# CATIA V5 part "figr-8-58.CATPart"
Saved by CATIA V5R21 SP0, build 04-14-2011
Part number: Part1
Bounding box of the stored display mesh (mm): x -50.499 to 50.499, y -68.48 to 68.48, z -46 to 50
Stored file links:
  D:\CATIA V5R21 E-RESOURCES\CATIA-V5R21\catia-v5r21-prt\c08-catia-v5r20-prt\c08-catia-v5r21-figr-8-58.CATPart
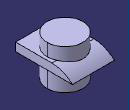
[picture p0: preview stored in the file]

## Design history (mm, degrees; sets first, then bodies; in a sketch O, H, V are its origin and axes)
Body1 (main body)
  Sketch1 on xy-plane, origin (0, 0, 0), H (1, 0, 0), V (0, 1, 0)
    line L1 (-50.499, 68.4797) -> (50.499, 68.4797)
    line L2 (50.499, 68.4797) -> (50.499, -68.4797)
    line L3 (50.499, -68.4797) -> (-50.499, -68.4797)
    line L4 (-50.499, -68.4797) -> (-50.499, 68.4797)
    axis line L5 (50.499, -68.4797) -> (-50.499, 68.4797)
    horizontal: L1 H, L3 H
    vertical: L2 V, L4 V
    midpoint: O L5
  Pad1: profile Sketch1, direction (0, 0, 1), length 20
  Fillet1: radius 71, on edge [face of Pad1 | face of Pad1]
  Body2
    Sketch2 on xy-plane, origin (0, 0, 0), H (1, 0, 0), V (0, 1, 0)
      circle A1 centre (0, 0) radius 43.2524
      point P1 (0, 43.2524)
      coincidence: A1 P1, P1 V
    Pad2: profile Sketch2, direction (0, 0, 1), length 50, opposite side length 46
  Assemble1: tool Body2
